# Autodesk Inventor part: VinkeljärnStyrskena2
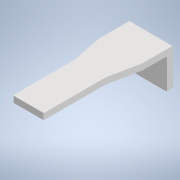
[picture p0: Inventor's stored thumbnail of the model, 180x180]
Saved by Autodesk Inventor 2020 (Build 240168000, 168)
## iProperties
Created: 2019-07
Part Number: VinkeljärnStyrskena2
Material: Generic
Document SubType Name: Modeling
Designer: cl
Density: 1 g/cm^3
Appearance: Default
Author: cl
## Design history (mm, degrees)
sketch "Sketch1"
  geometry: L1 (0, 0)-(70, 0); L2 (70, 0)-(70, 60); L3 (70, 60)-(0, 60); L4 (0, 60)-(0, 0)
  constraints: 8 end point, 2 parallel, 1 horizontal, 1 perpendicular
  dimensions: "d0" = 70 distance of L3.end L2.end; "d1" = 60 distance of L2.end L1.end
extrude "Extrusion1" new body sketch "Sketch1" distance "d2" = 10; taper "d3" = 0 deg
sketch "Sketch3"
  geometry: L1 (0, 0)-(70, 0) reference; L2 (0, 0)-(0, -50); L3 (0, -50)-(10, -100); L4 (10, -100)-(10, -200); L5 (10, -200)-(60, -200); L6 (60, -200)-(60, -100); L7 (60, -100)-(70, -50); L8 (70, -50)-(70, 0)
  constraints: 14 end point, 2 parallel, 2 perpendicular, 1 vertical
  dimensions: "d4" = 50 distance of L1.start L2.end; "d5" = 50 distance between parallel lines of L6 L4; "d6" = 200 distance between parallel lines of L1 L5; "d7" = 100 distance of L3.end L4.end; "d8" = 10 distance between parallel lines of L2 L4; "d9" = 50 distance of L7.end L1.end; "d10" = 100 distance of L5.end L6.end
extrude "Extrusion2" join sketch "Sketch3" distance "d11" = 10; taper "d12" = 0 deg
fillet "Fillet1" dims "d13" = 2
body "Solid1"
